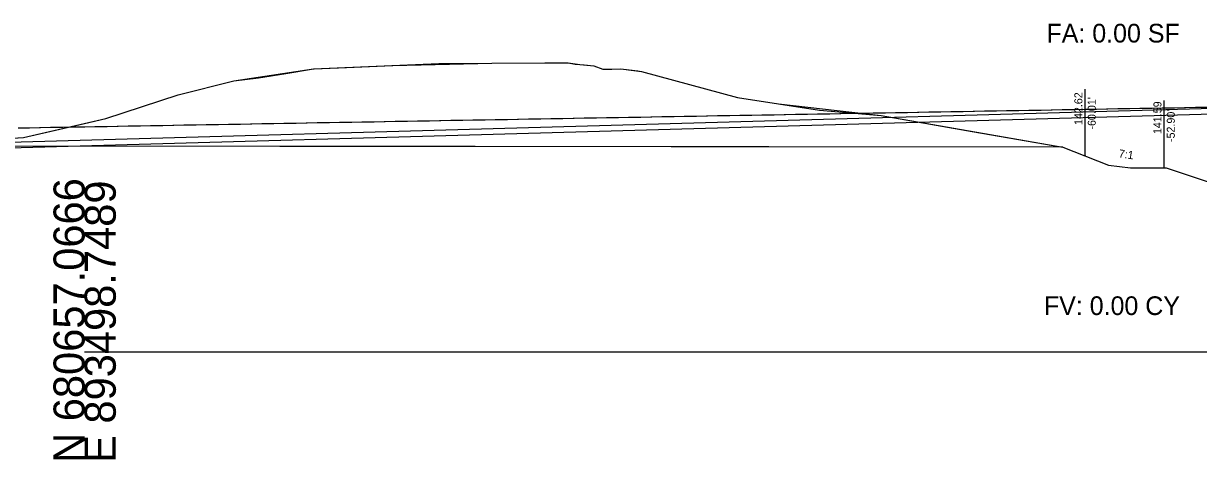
# Model space of a CAD drawing. Extents: x -100 to 4303, y -13 to 10775.
# Drawn here: x -5.5 to 100.2, y 9490.3 to 9529.5 of the extents above; entities that cross this region are included whole.
import ezdxf

# ---------------------------------------------------------------- set-up
doc = ezdxf.new("R2010")
doc.units = 0
for name, color, linetype in [('CONST_LV3', 7, 'Continuous'), ('Draft_XS_Grid', 7, 'Continuous'), ('DTM_CORRIDOR', 7, 'Continuous'), ('DTM_P_FINISHED_GRADE', 7, 'Continuous'), ('DTM_X_GROUND', 7, 'Continuous'), ('X_PROFILES_1', 7, 'Continuous'), ('XS_CELL', 7, 'Continuous'), ('XS_M_SHAPES_EARTHWORK', 7, 'Continuous'), ('XS_P_DR_GRAVEL', 7, 'Continuous'), ('XS_P_GROUND', 7, 'Continuous'), ('XS_P_TX_CLEARZONE', 7, 'Continuous'), ('XS_P_TX_FS_BS', 7, 'Continuous'), ('XS_SHEET_EW_TX_AREA', 7, 'Continuous'), ('XS_SHEET_EW_TX_VOLUME', 7, 'Continuous'), ('XS_X_EXCESS', 7, 'Continuous')]:
    doc.layers.add(name, color=color, linetype=linetype)

msp = doc.modelspace()

# ---------------------------------------------------------------- linework, layer by layer
at = {"layer": 'CONST_LV3'}
msp.add_lwpolyline([(-5.97, 9520.13), (-5.07, 9520.15), (-4.97, 9520.15), (-4.07, 9520.17), (-3.97, 9520.17), (-3.07, 9520.19), (-2.97, 9520.19), (-2.07, 9520.2), (-1.97, 9520.2), (-1.07, 9520.22), (-0.97, 9520.22), (-0.07, 9520.24), (0.03, 9520.24), (0.93, 9520.26), (1.03, 9520.26), (1.93, 9520.27), (2.03, 9520.27), (2.93, 9520.29), (3.03, 9520.29), (3.93, 9520.31), (4.03, 9520.31), (4.93, 9520.33), (5.03, 9520.33), (5.93, 9520.34), (6.03, 9520.34), (6.93, 9520.36), (7.03, 9520.36), (7.93, 9520.38), (8.03, 9520.38), (8.93, 9520.4), (9.03, 9520.4), (9.93, 9520.41), (10.03, 9520.41), (10.93, 9520.43), (11.03, 9520.43), (11.93, 9520.45), (12.03, 9520.45), (12.93, 9520.47), (13.03, 9520.47), (13.93, 9520.48), (14.03, 9520.48), (14.93, 9520.5), (15.03, 9520.5), (15.93, 9520.52), (16.03, 9520.52), (16.93, 9520.54), (17.03, 9520.54), (17.93, 9520.55), (18.03, 9520.55), (18.93, 9520.57), (19.03, 9520.57), (19.93, 9520.59), (20.03, 9520.59), (20.93, 9520.61), (21.03, 9520.61), (21.93, 9520.62), (22.03, 9520.62), (22.93, 9520.64), (23.03, 9520.64), (23.93, 9520.66), (24.03, 9520.66), (24.93, 9520.68), (25.03, 9520.68), (25.93, 9520.69), (26.03, 9520.69), (26.93, 9520.71), (27.03, 9520.71), (27.93, 9520.73), (28.03, 9520.73), (28.93, 9520.75), (29.03, 9520.75), (29.93, 9520.76), (30.03, 9520.76), (30.93, 9520.78), (31.03, 9520.78), (31.93, 9520.8), (32.03, 9520.8), (32.93, 9520.82), (33.03, 9520.82), (33.93, 9520.83), (34.03, 9520.83), (34.93, 9520.85), (35.03, 9520.85), (35.93, 9520.87), (36.03, 9520.87), (36.93, 9520.89), (37.03, 9520.89), (37.93, 9520.9), (38.03, 9520.9), (38.93, 9520.92), (39.03, 9520.92), (39.93, 9520.94), (40.03, 9520.94), (40.93, 9520.96), (41.03, 9520.96), (41.93, 9520.97), (42.03, 9520.97), (42.93, 9520.99), (43.03, 9520.99), (43.93, 9521.01), (44.03, 9521.01), (44.93, 9521.03), (45.03, 9521.03), (45.93, 9521.04), (46.03, 9521.04), (46.93, 9521.06), (47.03, 9521.06), (47.93, 9521.08), (48.03, 9521.08), (48.93, 9521.1), (49.03, 9521.1), (49.93, 9521.11), (50.03, 9521.11), (50.93, 9521.13), (51.03, 9521.13), (51.93, 9521.15), (52.03, 9521.15), (52.93, 9521.17), (53.03, 9521.17), (53.93, 9521.18), (54.03, 9521.18), (54.93, 9521.2), (55.03, 9521.2), (55.93, 9521.22), (56.03, 9521.22), (56.93, 9521.24), (57.03, 9521.24), (57.93, 9521.25), (58.03, 9521.25), (58.93, 9521.27), (59.03, 9521.27), (59.93, 9521.29), (60.03, 9521.29), (60.93, 9521.31), (61.03, 9521.31), (61.93, 9521.32), (62.03, 9521.32), (62.93, 9521.34), (63.03, 9521.34), (63.93, 9521.36), (64.03, 9521.36), (64.93, 9521.38), (65.03, 9521.38), (65.93, 9521.39), (66.03, 9521.39), (66.93, 9521.41), (67.03, 9521.41), (67.93, 9521.43), (68.03, 9521.43), (68.93, 9521.45), (69.03, 9521.45), (69.93, 9521.46), (70.03, 9521.46), (70.93, 9521.48), (71.03, 9521.48), (71.93, 9521.5), (72.03, 9521.5), (72.93, 9521.52), (73.03, 9521.52), (73.93, 9521.53), (74.03, 9521.53), (74.93, 9521.55), (75.03, 9521.55), (75.93, 9521.57), (76.03, 9521.57), (76.93, 9521.59), (77.03, 9521.59), (77.93, 9521.6), (78.03, 9521.6), (78.93, 9521.62), (79.03, 9521.62), (79.93, 9521.64), (80.03, 9521.64), (80.93, 9521.66), (81.03, 9521.66), (81.93, 9521.67), (82.03, 9521.67), (82.93, 9521.69), (83.03, 9521.69), (83.93, 9521.71), (84.03, 9521.71), (84.93, 9521.73), (85.03, 9521.73), (85.93, 9521.74), (86.03, 9521.74), (86.93, 9521.76), (87.03, 9521.76), (87.93, 9521.78), (88.03, 9521.78), (88.93, 9521.8), (89.03, 9521.8), (89.93, 9521.81), (90.03, 9521.81), (90.93, 9521.83), (91.03, 9521.83), (91.93, 9521.85), (92.03, 9521.85), (92.93, 9521.87), (93.03, 9521.87), (93.93, 9521.88), (94.03, 9521.88), (94.93, 9521.9), (95.03, 9521.9), (95.93, 9521.92), (96.03, 9521.92), (96.93, 9521.94), (97.03, 9521.94), (97.93, 9521.95), (98.03, 9521.95), (98.93, 9521.97), (99.03, 9521.97), (99.93, 9521.99), (100.03, 9521.99), (100.93, 9522.01)], dxfattribs=at)
at = {"layer": 'DTM_P_FINISHED_GRADE'}
msp.add_lwpolyline([(-5.97, 9520.13), (-5.07, 9520.15), (-4.97, 9520.15), (-4.07, 9520.17), (-3.97, 9520.17), (-3.07, 9520.19), (-2.97, 9520.19), (-2.07, 9520.2), (-1.97, 9520.2), (-1.07, 9520.22), (-0.97, 9520.22), (-0.07, 9520.24), (0.03, 9520.24), (0.93, 9520.26), (1.03, 9520.26), (1.93, 9520.27), (2.03, 9520.27), (2.93, 9520.29), (3.03, 9520.29), (3.93, 9520.31), (4.03, 9520.31), (4.93, 9520.33), (5.03, 9520.33), (5.93, 9520.34), (6.03, 9520.34), (6.93, 9520.36), (7.03, 9520.36), (7.93, 9520.38), (8.03, 9520.38), (8.93, 9520.4), (9.03, 9520.4), (9.93, 9520.41), (10.03, 9520.41), (10.93, 9520.43), (11.03, 9520.43), (11.93, 9520.45), (12.03, 9520.45), (12.93, 9520.47), (13.03, 9520.47), (13.93, 9520.48), (14.03, 9520.48), (14.93, 9520.5), (15.03, 9520.5), (15.93, 9520.52), (16.03, 9520.52), (16.93, 9520.54), (17.03, 9520.54), (17.93, 9520.55), (18.03, 9520.55), (18.93, 9520.57), (19.03, 9520.57), (19.93, 9520.59), (20.03, 9520.59), (20.93, 9520.61), (21.03, 9520.61), (21.93, 9520.62), (22.03, 9520.62), (22.93, 9520.64), (23.03, 9520.64), (23.93, 9520.66), (24.03, 9520.66), (24.93, 9520.68), (25.03, 9520.68), (25.93, 9520.69), (26.03, 9520.69), (26.93, 9520.71), (27.03, 9520.71), (27.93, 9520.73), (28.03, 9520.73), (28.93, 9520.75), (29.03, 9520.75), (29.93, 9520.76), (30.03, 9520.76), (30.93, 9520.78), (31.03, 9520.78), (31.93, 9520.8), (32.03, 9520.8), (32.93, 9520.82), (33.03, 9520.82), (33.93, 9520.83), (34.03, 9520.83), (34.93, 9520.85), (35.03, 9520.85), (35.93, 9520.87), (36.03, 9520.87), (36.93, 9520.89), (37.03, 9520.89), (37.93, 9520.9), (38.03, 9520.9), (38.93, 9520.92), (39.03, 9520.92), (39.93, 9520.94), (40.03, 9520.94), (40.93, 9520.96), (41.03, 9520.96), (41.93, 9520.97), (42.03, 9520.97), (42.93, 9520.99), (43.03, 9520.99), (43.93, 9521.01), (44.03, 9521.01), (44.93, 9521.03), (45.03, 9521.03), (45.93, 9521.04), (46.03, 9521.04), (46.93, 9521.06), (47.03, 9521.06), (47.93, 9521.08), (48.03, 9521.08), (48.93, 9521.1), (49.03, 9521.1), (49.93, 9521.11), (50.03, 9521.11), (50.93, 9521.13), (51.03, 9521.13), (51.93, 9521.15), (52.03, 9521.15), (52.93, 9521.17), (53.03, 9521.17), (53.93, 9521.18), (54.03, 9521.18), (54.93, 9521.2), (55.03, 9521.2), (55.93, 9521.22), (56.03, 9521.22), (56.93, 9521.24), (57.03, 9521.24), (57.93, 9521.25), (58.03, 9521.25), (58.93, 9521.27), (59.03, 9521.27), (59.93, 9521.29), (60.03, 9521.29), (60.93, 9521.31), (61.03, 9521.31), (61.93, 9521.32), (62.03, 9521.32), (62.93, 9521.34), (63.03, 9521.34), (63.93, 9521.36), (64.03, 9521.36), (64.93, 9521.38), (65.03, 9521.38), (65.93, 9521.39), (66.03, 9521.39), (66.93, 9521.41), (67.03, 9521.41), (67.93, 9521.43), (68.03, 9521.43), (68.93, 9521.45), (69.03, 9521.45), (69.93, 9521.46), (70.03, 9521.46), (70.93, 9521.48), (71.03, 9521.48), (71.93, 9521.5), (72.03, 9521.5), (72.93, 9521.52), (73.03, 9521.52), (73.93, 9521.53), (74.03, 9521.53), (74.93, 9521.55), (75.03, 9521.55), (75.93, 9521.57), (76.03, 9521.57), (76.93, 9521.59), (77.03, 9521.59), (77.93, 9521.6), (78.03, 9521.6), (78.93, 9521.62), (79.03, 9521.62), (79.93, 9521.64), (80.03, 9521.64), (80.93, 9521.66), (81.03, 9521.66), (81.93, 9521.67), (82.03, 9521.67), (82.93, 9521.69), (83.03, 9521.69), (83.93, 9521.71), (84.03, 9521.71), (84.93, 9521.73), (85.03, 9521.73), (85.93, 9521.74), (86.03, 9521.74), (86.93, 9521.76), (87.03, 9521.76), (87.93, 9521.78), (88.03, 9521.78), (88.93, 9521.8), (89.03, 9521.8), (89.93, 9521.81), (90.03, 9521.81), (90.93, 9521.83), (91.03, 9521.83), (91.93, 9521.85), (92.03, 9521.85), (92.93, 9521.87), (93.03, 9521.87), (93.93, 9521.88), (94.03, 9521.88), (94.93, 9521.9), (95.03, 9521.9), (95.93, 9521.92), (96.03, 9521.92), (96.93, 9521.94), (97.03, 9521.94), (97.93, 9521.95), (98.03, 9521.95), (98.93, 9521.97), (99.03, 9521.97), (99.93, 9521.99), (100.03, 9521.99), (100.93, 9522.01)], dxfattribs=at)
at = {"layer": 'DTM_X_GROUND'}
for points in [[(0, 9520.52), (1.92, 9520.97), (8.42, 9523.11), (13.41, 9524.35), (15.63, 9524.63), (20.59, 9525.44), (20.65, 9525.45), (23.57, 9525.57), (31.85, 9525.91), (41.41, 9525.98), (43.49, 9525.99), (44.13, 9525.87), (44.92, 9525.79), (45.79, 9525.71), (46.6, 9525.41), (48.24, 9525.43), (49.75, 9525.27), (50.09, 9525.21), (58.73, 9522.85), (66.1, 9521.73), (71.65, 9521.24), (87.99, 9518.4), (92.11, 9516.79), (94.09, 9516.55), (97.28, 9516.53)], [(-99.54, 9518.72), (-80.95, 9518.76), (-79.09, 9518.42), (-74.34, 9518.9), (-74.2, 9518.87), (-74, 9518.82), (-72.71, 9518.65), (-68.08, 9519.06), (-53.53, 9519.32), (-39.49, 9519.23), (-36.89, 9518.69), (-30.4, 9518.08), (-23.07, 9518.12), (-12.34, 9518.88), (-5.51, 9519.28), (-3.41, 9519.74), (0, 9520.52)], [(97.28, 9516.53), (103.57, 9514.43)]]:
    msp.add_lwpolyline(points, dxfattribs=at)
at = {"layer": 'XS_CELL'}
msp.add_line((0, 9500), (150, 9500), dxfattribs=at)
msp.add_line((0, 9500), (150, 9500), dxfattribs=at)
at = {"layer": 'XS_M_SHAPES_EARTHWORK'}
msp.add_lwpolyline([(87.99, 9518.4), (35.14, 9518.45), (-17.71, 9518.5), (-5.51, 9519.28), (1.92, 9520.97), (8.42, 9523.11), (13.41, 9524.35), (15.63, 9524.63), (18.11, 9525.03), (20.59, 9525.44), (31.85, 9525.91), (41.41, 9525.98), (43.49, 9525.99), (44.53, 9525.83), (45.79, 9525.71), (46.6, 9525.41), (48.24, 9525.43), (50.09, 9525.21), (54.41, 9524.03), (58.73, 9522.85), (62.41, 9522.29), (66.1, 9521.73), (71.65, 9521.24)], close=True, dxfattribs=at)
at = {"layer": 'XS_P_DR_GRAVEL'}
for p, q in [((113.8, 9522.23), (-17.71, 9518.5)), ((113.82, 9521.73), (-17.69, 9518))]:
    msp.add_line(p, q, dxfattribs=at)
at = {"layer": 'XS_P_GROUND'}
msp.add_line((87.99, 9518.4), (-17.71, 9518.5), dxfattribs=at)
at = {"layer": 'XS_P_TX_CLEARZONE'}
for p, q in [((89.99, 9517.62), (89.99, 9523.62)), ((89.99, 9517.62), (89.99, 9523.62)), ((89.99, 9517.62), (89.99, 9523.62)), ((89.99, 9517.62), (89.99, 9523.62)), ((89.99, 9517.62), (89.99, 9523.62)), ((97.1, 9516.59), (97.1, 9522.59)), ((97.1, 9516.59), (97.1, 9522.59)), ((97.1, 9516.59), (97.1, 9522.59)), ((97.1, 9516.59), (97.1, 9522.59)), ((97.1, 9516.59), (97.1, 9522.59))]:
    msp.add_line(p, q, dxfattribs=at)
at = {"layer": 'XS_X_EXCESS'}
msp.add_lwpolyline([(87.99, 9518.4), (-17.71, 9518.5), (-5.51, 9519.28), (0, 9520.52), (1.92, 9520.97), (8.42, 9523.11), (13.41, 9524.35), (20.59, 9525.44), (27.71, 9525.74), (36.63, 9525.94), (43.49, 9525.99), (44.53, 9525.83), (45.79, 9525.71), (46.6, 9525.41), (47.42, 9525.42), (48.24, 9525.43), (50.09, 9525.21), (54.41, 9524.03), (58.73, 9522.85), (62.41, 9522.29), (71.65, 9521.24), (79.82, 9519.82)], close=True, dxfattribs=at)

# ---------------------------------------------------------------- texts
at = {"layer": 'Draft_XS_Grid'}
msp.add_text('-', height=0.0001, dxfattribs=at).set_placement((0, 9500))
at = {"layer": 'DTM_CORRIDOR'}
for height, p in [(0.001, (95.79, 9517.02)), (0.12, (97.06, 9516.53))]:
    msp.add_text('X', height=height, dxfattribs=at).set_placement(p)
at = {"layer": 'X_PROFILES_1'}
msp.add_text('X', height=0.12, dxfattribs=at).set_placement((89.96, 9517.56))
at = {"layer": 'XS_CELL'}
for s, p in [('N 680657.0666', (0, 9490)), ('N 680657.0666', (0, 9490)), ('E 893498.7489', (2.8, 9490)), ('E 893498.7489', (2.8, 9490))]:
    msp.add_text(s, height=2.8, rotation=90, dxfattribs=at).set_placement(p)
at = {"layer": 'XS_P_TX_CLEARZONE'}
for s, p in [('142.62', (89.75, 9520.39)), ('142.62', (89.75, 9520.39)), ('142.62', (89.75, 9520.39)), ('142.62', (89.75, 9520.39)), ('142.62', (89.75, 9520.39)), ("-60.01'", (90.95, 9519.98)), ("-60.01'", (90.95, 9519.98)), ("-60.01'", (90.95, 9519.98)), ("-60.01'", (90.95, 9519.98)), ("-60.01'", (90.95, 9519.98)), ('141.59', (96.86, 9519.57)), ('141.59', (96.86, 9519.57)), ('141.59', (96.86, 9519.57)), ('141.59', (96.86, 9519.57)), ('141.59', (96.86, 9519.57)), ("-52.90'", (98.06, 9518.86)), ("-52.90'", (98.06, 9518.86)), ("-52.90'", (98.06, 9518.86)), ("-52.90'", (98.06, 9518.86)), ("-52.90'", (98.06, 9518.86))]:
    msp.add_text(s, height=0.72, rotation=90, dxfattribs=at).set_placement(p)
at = {"layer": 'XS_P_TX_FS_BS'}
msp.add_text('7:1', height=0.72, rotation=351.7517, dxfattribs=at).set_placement((92.98, 9517.49))
at = {"layer": 'XS_SHEET_EW_TX_AREA'}
msp.add_text('FA: 0.00 SF', height=1.68, dxfattribs=at).set_placement((86.52, 9527.81))
at = {"layer": 'XS_SHEET_EW_TX_VOLUME'}
msp.add_text('FV: 0.00 CY', height=1.68, dxfattribs=at).set_placement((86.29, 9503.3))

doc.saveas('drawing.dxf')
